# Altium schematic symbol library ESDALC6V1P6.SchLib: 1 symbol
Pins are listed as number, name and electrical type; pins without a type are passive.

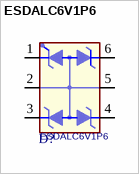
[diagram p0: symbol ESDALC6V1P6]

## ESDALC6V1P6
designator D?
footprint ST_SOT666IP
pins: 1, 2, 3, 4, 5, 6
